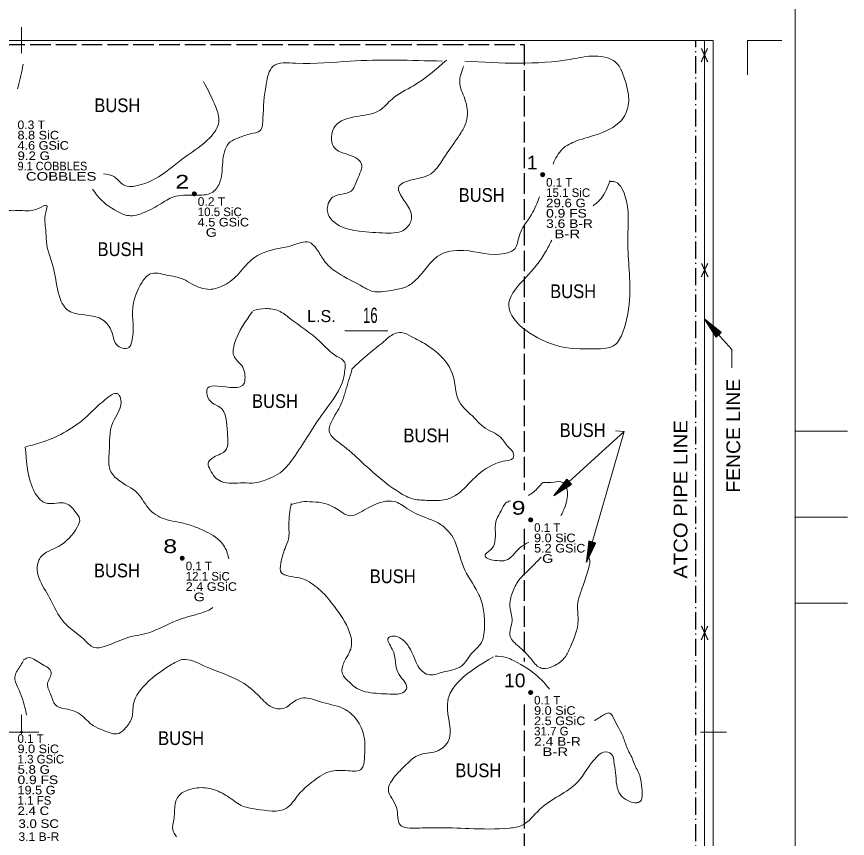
# Model space of a CAD drawing. Extents: x -496 to 480, y -452 to 700.
# Drawn here: x -2.8 to 480.3, y -61.9 to 416.2 of the extents above; entities that cross this region are included whole.
import ezdxf
from ezdxf.enums import TextEntityAlignment as Align

# ---------------------------------------------------------------- set-up
doc = ezdxf.new("R2010")
doc.units = 0
doc.header["$LTSCALE"] = 2
doc.header["$PDMODE"] = 32
doc.header["$PDSIZE"] = 1
doc.linetypes.add('DOT_DASHED', pattern=[7.7, 5, -1.2, 0.3, -1.2])
doc.linetypes.add('LONG_DASHED', pattern=[7.5, 6, -1.5])
doc.layers.add('3', color=7, linetype='Continuous', lineweight=13)

msp = doc.modelspace()

# ---------------------------------------------------------------- linework, layer by layer
at = {"layer": '3'}
for p, q in [((-0.017, 394.973), (-0.017, 409.973)), ((397.281, -433.821), (397.281, 402.339)), ((422.281, 402.339), (442.281, 402.339)), ((422.281, 402.339), (422.281, 382.339)), ((188.066, 233.284), (213.066, 233.284)), ((350.412, 174.9), (328.652, 98.828)), ((480.331, 174.973), (449.983, 174.973)), ((480.331, 124.973), (449.983, 124.973)), ((480.331, 74.973), (449.983, 74.973)), ((-0.017, -0.976), (-0.017, 9.973)), ((-10.017, -0.027), (9.983, -0.027)), ((394.983, -0.027), (409.983, -0.027))]:
    msp.add_line(p, q, dxfattribs=at)
at = {"layer": '3', "linetype": 'DOT_DASHED', "lineweight": 25}
msp.add_line((392.281, -402.333), (392.281, 402.339), dxfattribs=at)
at = {"layer": '3', "linetype": 'LONG_DASHED', "lineweight": 25}
for p, q in [((-400, 400), (292.281, 400)), ((292.281, 400), (292.281, 140.671)), ((292.281, 118.237), (292.281, 41.076)), ((292.281, 15.922), (292.281, -71.709))]:
    msp.add_line(p, q, dxfattribs=at)
at = {"layer": '3'}
for points in [[(449.983, -450.027), (449.983, 399.973), (449.983, 699.973), (-450.017, 699.973), (-450.017, 49.973), (-450.017, -450.027)], [(402.281, -402.333), (402.281, 402.339), (-402.391, 402.339)], [(413.177, 211.851), (413.177, 222.551), (397.391, 240.008)], [(345.39, 175.178), (350.412, 174.9), (309.682, 137.561)]]:
    msp.add_lwpolyline(points, dxfattribs=at)
at = {"layer": '3', "lineweight": 25}
for points in [[(397.391, 240.008), (403.956, 229.766), (406.923, 232.449)], [(309.682, 137.561), (319.879, 144.195), (317.176, 147.144)], [(328.652, 98.828), (333.875, 109.816), (330.029, 110.916)]]:
    msp.add_lwpolyline(points, close=True, dxfattribs=at)
for points in [[(403.978, 229.918), (397.775, 239.582), (406.692, 232.459), (404.078, 230.067), (398.27, 239.035), (406.435, 232.489), (404.075, 230.295), (398.791, 238.458), (406.143, 232.487), (404.147, 230.536), (399.369, 237.788), (405.838, 232.533), (404.163, 230.843), (400.064, 236.985), (405.515, 232.504), (404.211, 231.177), (400.816, 236.123), (405.087, 232.494), (404.212, 231.528), (401.61, 235.148), (404.663, 232.576), (404.187, 231.942), (402.625, 234.056), (404.131, 232.619)], [(319.726, 144.216), (310.105, 137.948), (317.167, 146.913), (319.576, 144.315), (310.648, 138.446), (317.139, 146.655), (319.349, 144.31), (311.222, 138.971), (317.143, 146.363), (319.107, 144.381), (311.888, 139.554), (317.098, 146.058), (318.8, 144.394), (312.686, 140.254), (317.13, 145.736), (318.466, 144.44), (313.543, 141.011), (317.143, 145.307), (318.115, 144.439), (314.512, 141.812), (317.064, 144.883), (317.701, 144.411), (315.598, 142.835), (317.024, 144.35)], [(333.734, 109.754), (328.81, 99.38), (330.142, 110.714), (333.555, 109.759), (329.013, 100.088), (330.253, 110.48), (333.363, 109.636), (329.227, 100.836), (330.409, 110.233), (333.12, 109.571), (329.49, 101.681), (330.531, 109.95), (332.851, 109.421), (329.805, 102.695), (330.727, 109.691), (332.542, 109.285), (330.139, 103.789), (330.961, 109.333), (332.244, 109.101), (330.547, 104.978), (331.116, 108.93), (331.905, 108.861), (330.937, 106.418), (331.361, 108.455)]]:
    msp.add_lwpolyline(points, dxfattribs=at)
at = {"layer": '3', "lineweight": 35}
for centre in [(303.111, 324.24), (100.488, 313.083), (296.124, 123.414), (93.501, 101.1), (296.124, 23.001)]:
    msp.add_circle(centre, 1, dxfattribs=at)
at = {"layer": '3'}
for points in [[(257.828, 390.252), (319.807, 391.442), (333.513, 393.228), (345.432, 389.656), (351.392, 377.751), (353.18, 367.036), (350.2, 357.512), (335.897, 347.988), (322.786, 343.821), (314.443, 339.059), (309.134, 330.396)], [(-2.372, 374.211), (-2.006, 375.37), (0.973, 388.466)], [(244.717, 390.252), (191.081, 390.252), (159.496, 389.061), (146.385, 387.275), (142.214, 376.561), (140.426, 356.917), (138.638, 349.774), (133.274, 347.988), (126.123, 345.607), (121.355, 343.226), (117.184, 333.107), (115.396, 320.011), (111.224, 314.058), (104.073, 312.273), (95.729, 312.273), (89.77, 311.677), (81.427, 307.511), (71.296, 302.153), (62.356, 300.367), (55.801, 302.748), (43.882, 312.273), (41.313, 315.866)], [(257.232, 387.275), (254.848, 377.751), (257.828, 368.227), (259.02, 356.322), (256.636, 350.369), (252.464, 343.821), (244.717, 332.511), (238.161, 324.773), (225.051, 320.606), (219.687, 317.63), (224.455, 306.32), (226.838, 298.582), (223.263, 292.629), (211.94, 290.248), (196.445, 291.438), (186.314, 293.82), (177.971, 302.748), (180.95, 311.082), (191.677, 314.654), (195.253, 321.201), (197.637, 330.726), (189.294, 336.083), (182.142, 339.655), (180.354, 344.417), (182.142, 352.155), (195.253, 358.108), (208.364, 361.679), (215.515, 368.227), (228.03, 375.965), (247.101, 390.847)], [(47.611, 324.687), (54.013, 322.987), (59.377, 318.225), (68.912, 318.225), (79.639, 322.987), (95.729, 334.892), (109.436, 345.607), (114.8, 355.131), (113.012, 363.465), (105.861, 378.346)], [(301.264, 311.258), (296.565, 300.963), (289.413, 288.462), (287.029, 281.319), (281.07, 278.343), (257.232, 280.129), (241.737, 276.557), (236.97, 271.795), (230.414, 264.057), (224.455, 259.294), (214.919, 256.913), (204.192, 256.318), (197.041, 259.89), (182.142, 268.223), (175.587, 274.771), (171.415, 281.319), (167.243, 284.891), (157.708, 283.105), (149.365, 281.319), (133.87, 274.771), (125.527, 265.842), (116.588, 259.294), (109.436, 257.509), (99.305, 260.485), (93.942, 263.461), (84.406, 265.842), (74.871, 266.438), (70.104, 261.676), (64.74, 246.794), (64.144, 227.15), (62.356, 223.579), (55.205, 225.365), (53.417, 229.531), (51.629, 234.889), (45.074, 240.841), (26.599, 245.604), (21.832, 253.937), (18.852, 268.819), (14.68, 283.7), (14.084, 292.034), (14.084, 302.153), (14.68, 306.32), (9.913, 304.534), (-0.814, 303.344), (-10.35, 304.534), (-10.946, 314.654), (-16.309, 342.036), (-14.521, 353.346), (-13.809, 355.669)], [(342.261, 320.153), (344.565, 320.153), (350.903, 312.096), (352.631, 287.351), (353.783, 253.973), (349.75, 232.68), (345.141, 225.199), (333.618, 222.897), (309.996, 225.199), (283.494, 249.944), (293.288, 264.331), (304.811, 279.294), (308.352, 286.08)], [(332.524, 306.076), (337.075, 310.37), (342.261, 320.728)], [(134.694, 245.232), (142.035, 246.279), (149.638, 244.97), (155.93, 240.78), (173.497, 227.162), (183.46, 218.52), (187.917, 215.116), (188.179, 211.711), (186.606, 203.593), (174.283, 183.952), (158.29, 159.597), (149.114, 149.908), (143.608, 147.289), (135.742, 144.932), (128.925, 144.932), (116.079, 145.718), (112.408, 148.336), (109.786, 152.526), (108.475, 156.193), (111.884, 159.859), (118.7, 163.787), (119.749, 174.001), (115.292, 188.928), (111.097, 191.285), (107.951, 195.998), (108.213, 199.927), (113.981, 201.236), (129.45, 202.807), (129.974, 207.521), (128.663, 212.235), (123.42, 219.044), (123.944, 226.115), (134.431, 244.708)], [(191.849, 210.926), (202.337, 220.353), (210.727, 227.162), (216.757, 231.614), (220.952, 232.4), (226.72, 230.043), (235.372, 225.329), (242.975, 219.568), (251.103, 206.997), (254.511, 192.332), (263.425, 182.643), (268.407, 177.667), (278.894, 171.12), (283.089, 165.882), (286.235, 161.692), (285.449, 158.812), (283.089, 158.026), (277.321, 156.716), (263.95, 148.336), (253.2, 138.123), (246.908, 135.242), (236.683, 134.719), (228.031, 135.504), (219.641, 139.432), (193.423, 161.168), (186.868, 166.668), (179.002, 175.048), (180.838, 181.595), (186.344, 191.808), (188.441, 198.355), (192.112, 210.402)], [(2.51, 165.929), (12.562, 168.797), (38.124, 183.715), (44.442, 189.74), (48.463, 193.182), (52.771, 196.338), (55.643, 196.912), (57.654, 194.043), (53.059, 179.986), (51.048, 163.06), (51.623, 152.159), (56.505, 146.421), (67.419, 138.962), (74.599, 129.208), (84.652, 123.471), (91.258, 122.036), (99.012, 120.028), (105.905, 117.159), (116.245, 110.274), (119.979, 103.102), (120.525, 100.678)], [(111.232, 72.472), (110.788, 72.12), (102.746, 68.677), (90.396, 64.948), (74.025, 57.776), (60.813, 54.62), (48.176, 49.743), (42.145, 49.169), (36.4, 53.759), (24.625, 63.8), (16.296, 78.144), (10.264, 89.332), (9.115, 94.209), (11.126, 101.668), (21.465, 107.979), (32.379, 119.168), (33.815, 124.045), (31.518, 127.774), (27.497, 132.077), (24.338, 133.225), (13.998, 133.225), (11.126, 134.946), (5.956, 143.265), (2.222, 165.642)], [(294.877, 137.528), (297.949, 139.757), (303.007, 144.99)], [(303.188, 145.171), (309.511, 145.351), (314.75, 145.171), (316.737, 142.644), (317.64, 138.494), (316.917, 133.803), (315.111, 128.57), (313.753, 125.781)], [(156.592, 132.107), (163.048, 133.886), (169.282, 133.886), (176.406, 132.997), (181.972, 130.551), (185.979, 128.104), (189.986, 125.881), (195.998, 127.215), (199.114, 128.994), (204.012, 131.662), (210.246, 133.886), (216.702, 134.109), (224.049, 130.106), (235.404, 124.546), (242.305, 121.656), (247.426, 117.653), (250.988, 112.983), (256.999, 96.082), (265.459, 80.961), (268.576, 71.844), (269.244, 62.281), (267.463, 52.052), (261.674, 45.603), (256.108, 38.487), (244.532, 34.707), (236.294, 33.373), (232.955, 35.374), (225.162, 49.828), (220.042, 54.721), (216.257, 55.833), (213.363, 54.721), (215.589, 48.272), (219.597, 33.373), (223.827, 24.922), (222.491, 23.366), (214.253, 22.032), (201.563, 23.143), (195.998, 24.922), (189.764, 29.815), (186.647, 33.817), (187.537, 40.489), (191.768, 49.384), (190.654, 58.501), (181.972, 72.955), (173.957, 82.295), (169.727, 85.631), (164.606, 88.744), (160.376, 89.856), (153.697, 91.19), (151.248, 92.524), (150.803, 98.084), (153.252, 106.756), (155.256, 112.316), (155.478, 120.544), (156.814, 132.997)], [(295.045, 110.46), (289.459, 106.737), (281.691, 99.881), (276.633, 99.7), (271.936, 100.603), (269.588, 102.407), (272.659, 105.835), (275.369, 110.707), (275.549, 117.564), (276.272, 123.698), (278.981, 128.751), (281.691, 133.262), (284.382, 134.487)], [(328.858, 102.596), (330.104, 101.144), (329.743, 95.009), (326.672, 85.265), (323.421, 73.537), (323.782, 64.696), (319.266, 49.539), (316.014, 43.404), (310.233, 38.713), (304.633, 36.908), (301.562, 37.449), (296.143, 42.682), (289.098, 49.9), (284.22, 55.493), (285.304, 64.696), (284.04, 72.996), (285.485, 81.115), (289.278, 88.333), (296.504, 95.731), (302.239, 101.756)], [(0.949, 41.816), (3.634, 43.158), (11.154, 39.939), (17.331, 34.574), (15.182, 28.135), (17.062, 21.697), (19.748, 15.796), (29.416, 12.577), (34.25, 10.163), (41.77, 3.725), (47.41, 1.042), (56.541, -0.836), (60.57, 2.383), (64.33, 8.821), (65.135, 16.332), (70.506, 25.989), (86.62, 38.866), (93.603, 42.085), (106.494, 38.329), (127.71, 29.208), (138.453, 20.624), (145.704, 14.455), (152.15, 13.65), (159.669, 18.478), (163.966, 19.82), (173.366, 17.674), (187.063, 13.65), (194.851, 7.212), (199.148, -2.445), (199.417, -15.321), (197.805, -21.491), (190.017, -22.564), (179.006, -23.101), (168.801, -29.27), (161.281, -36.245), (154.03, -44.293), (136.573, -44.829), (127.71, -42.683), (123.95, -40.269), (115.356, -34.904), (107.031, -32.489), (97.363, -33.562), (91.454, -37.05), (88.5, -51.535), (87.963, -56.632), (90.162, -60.935)], [(333.224, 6.623), (333.492, 6.781), (336.548, 8.66), (341.955, 11.008), (345.011, 6.781), (350.182, -3.551), (352.768, -10.595), (354.884, -14.587), (356.295, -18.344), (359.586, -25.388), (360.761, -32.667), (360.996, -37.598), (359.821, -40.416), (357.705, -41.12), (353.709, -40.416), (348.537, -36.659), (346.186, -30.789), (345.481, -23.509), (344.54, -17.17), (343.6, -13.413), (339.839, -11.534), (334.667, -14.352), (323.383, -29.145), (301.285, -45.112), (291.177, -54.27), (283.889, -55.913), (260.381, -56.148), (241.339, -55.679), (230.055, -55.913), (220.182, -54.035), (218.066, -43.938), (213.364, -33.606), (217.596, -25.388), (224.648, -18.109), (230.995, -13.413), (241.104, -11.299), (247.921, -5.899), (247.686, 16.174), (249.332, 22.513), (254.739, 29.793), (274.486, 43.646)], [(275.426, 44.116), (282.008, 43.412), (286.24, 41.533), (301.52, 31.201), (307.096, 24.89)], [(2.873, 9.804), (2.023, 14.186), (-2.274, 26.258), (-3.885, 31.891), (-0.931, 38.061), (0.949, 41.28)]]:
    msp.add_spline(points, degree=3, dxfattribs=at)
at = {"layer": '3', "lineweight": 35}
for points in [[(303.1, 325.127), (303.83, 324.723), (303.982, 323.874), (303.297, 323.346), (302.488, 323.577), (302.201, 324.335), (302.448, 324.897), (303.021, 325.065), (303.695, 324.571), (303.679, 323.829), (303.162, 323.571), (302.639, 323.74), (302.415, 324.386), (302.999, 324.852), (303.437, 324.318), (303.398, 323.835), (302.769, 323.97), (302.915, 324.605), (303.207, 324.054)], [(100.477, 313.97), (101.207, 313.566), (101.359, 312.717), (100.674, 312.189), (99.865, 312.42), (99.578, 313.178), (99.825, 313.74), (100.398, 313.908), (101.072, 313.414), (101.056, 312.672), (100.539, 312.414), (100.016, 312.583), (99.792, 313.229), (100.376, 313.695), (100.814, 313.161), (100.775, 312.678), (100.146, 312.813), (100.292, 313.448), (100.584, 312.897)], [(296.113, 124.301), (296.843, 123.897), (296.995, 123.048), (296.31, 122.52), (295.501, 122.751), (295.214, 123.509), (295.461, 124.071), (296.034, 124.239), (296.708, 123.745), (296.692, 123.003), (296.175, 122.745), (295.652, 122.914), (295.428, 123.56), (296.012, 124.026), (296.45, 123.492), (296.411, 123.009), (295.782, 123.144), (295.928, 123.779), (296.22, 123.228)], [(93.49, 101.987), (94.22, 101.583), (94.372, 100.734), (93.687, 100.206), (92.878, 100.437), (92.591, 101.195), (92.838, 101.757), (93.411, 101.925), (94.085, 101.431), (94.069, 100.689), (93.552, 100.431), (93.029, 100.6), (92.805, 101.246), (93.389, 101.712), (93.827, 101.178), (93.788, 100.695), (93.159, 100.83), (93.305, 101.465), (93.597, 100.914)], [(296.113, 23.888), (296.843, 23.484), (296.995, 22.635), (296.31, 22.107), (295.501, 22.338), (295.214, 23.096), (295.461, 23.658), (296.034, 23.826), (296.708, 23.332), (296.692, 22.59), (296.175, 22.332), (295.652, 22.501), (295.428, 23.147), (296.012, 23.613), (296.45, 23.079), (296.411, 22.596), (295.782, 22.731), (295.928, 23.366), (296.22, 22.815)]]:
    msp.add_spline(points, degree=3, dxfattribs=at)
at = {"layer": '3'}
for p in [(0, 0), (0.001, -0.011)]:
    msp.add_point(p, dxfattribs=at)

# ---------------------------------------------------------------- texts
for s, height, width, p in [('X', 8, 0.7, (397.181, 389.663)), ('BUSH', 8, 0.9, (55.723, 360.579)), ('BUSH', 8, 0.9, (267.628, 308.37)), ('BUSH', 8, 0.9, (57.606, 276.856)), ('X', 8, 0.7, (397.297, 264.639)), ('BUSH', 8, 0.9, (320.84, 252.398)), ('16', 8.89, 0.65, (202.864, 237.962)), ('BUSH', 8, 0.9, (147.418, 188.487)), ('BUSH', 8, 0.9, (326.361, 171.611)), ('BUSH', 8, 0.9, (235.502, 168.54)), ('BUSH', 8, 0.9, (55.499, 89.956)), ('BUSH', 8, 0.9, (215.92, 86.595)), ('X', 8, 0.7, (397.264, 53.58)), ('BUSH', 8, 0.9, (92.831, -7.581)), ('BUSH', 8, 0.9, (265.689, -26.302))]:
    msp.add_text(s, height=height, dxfattribs=dict(at, width=width)).set_placement(p, align=Align.CENTER)
for s, width, p in [('0.3 T      ', 1.05, (-2.317, 350.711)), ('8.8 SiC    ', 1.1, (-2.317, 344.711)), ('4.6 GSiC   ', 1.1, (-2.317, 338.711)), ('9.2 G      ', 1.15, (-2.317, 332.711)), ('9.1 COBBLES', 0.95, (-2.317, 326.711)), ('  COBBLES  ', 1.3, (-2.317, 320.711)), ('0.2 T      ', 1.05, (102.488, 306.083)), ('29.6 G     ', 1.15, (305.111, 305.24)), ('0.9 FS     ', 1.2, (305.111, 299.24)), ('4.5 GSiC   ', 1.1, (102.488, 294.083)), ('3.6 B-R    ', 1.2, (305.111, 293.24)), ('  G        ', 1.25, (102.488, 288.083)), ('  B-R      ', 1.3, (305.111, 287.24)), ('9.0 SiC    ', 1.1, (298.124, 110.414)), ('5.2 GSiC   ', 1.1, (298.124, 104.414)), ('  G        ', 1.25, (298.124, 98.414)), ('2.4 GSiC   ', 1.1, (95.501, 82.1)), ('  G        ', 1.25, (95.501, 76.1)), ('9.0 SiC    ', 1.1, (298.124, 10.001)), ('2.5 GSiC   ', 1.1, (298.124, 4.001)), ('2.4 B-R    ', 1.2, (298.124, -7.999)), ('9.0 SiC    ', 1.1, (-2.317, -12.313)), ('  B-R      ', 1.3, (298.124, -13.999)), ('5.8 G      ', 1.15, (-2.317, -24.313)), ('0.9 FS     ', 1.2, (-2.317, -30.313)), ('19.5 G     ', 1.1, (-2.317, -36.313)), ('2.4 C      ', 1.15, (-2.317, -48.313)), ('3.0 SC     ', 1.15, (-1.765, -55.82)), ('3.1 B-R    ', 1.05, (-1.765, -63.367))]:
    msp.add_text(s, height=5, dxfattribs=dict(at, width=width)).set_placement(p)
for s, width, p in [('  1', 1.05, (300.11, 327.24)), ('  2', 1.35, (97.487, 316.083)), ('  9', 1.35, (293.123, 126.414)), ('  8', 1.35, (90.5, 104.1)), (' 10', 1.05, (293.123, 26.001))]:
    msp.add_text(s, height=8, dxfattribs=dict(at, width=width)).set_placement(p, align=Align.RIGHT)
for s, p in [('0.1 T      ', (305.111, 317.24)), ('15.1 SiC   ', (305.111, 311.24)), ('10.5 SiC   ', (102.488, 300.083)), ('0.1 T      ', (298.124, 116.414)), ('0.1 T      ', (95.501, 94.1)), ('12.1 SiC   ', (95.501, 88.1)), ('0.1 T      ', (298.124, 16.001)), ('31.7 G     ', (298.124, -1.999)), ('0.1 T      ', (-2.317, -6.313)), ('1.3 GSiC   ', (-2.317, -18.313)), ('1.1 FS     ', (-2.317, -42.313))]:
    msp.add_text(s, height=5, dxfattribs=at).set_placement(p)
msp.add_text('L.S.', height=7, dxfattribs=at).set_placement((174.416, 238.457), align=Align.CENTER)
for s, width, p in [('FENCE LINE', 1.05, (417.967, 172.348)), ('ATCO PIPE LINE', 1.1, (387.298, 135.331))]:
    msp.add_text(s, height=8, rotation=90, dxfattribs=dict(at, width=width)).set_placement(p, align=Align.CENTER)

doc.saveas('drawing.dxf')
